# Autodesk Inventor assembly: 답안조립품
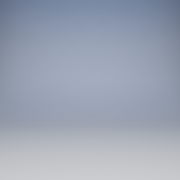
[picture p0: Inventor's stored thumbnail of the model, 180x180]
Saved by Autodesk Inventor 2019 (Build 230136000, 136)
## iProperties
Created: 2021-01
Part Number: 답안조립품
Material: 일반
Document SubType Name: Assembly
Designer: 3dpro10
Author: 3dpro10
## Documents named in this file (1)
- C:\Users\3dpro10\Desktop\710114V1012\답안조립품.iam
